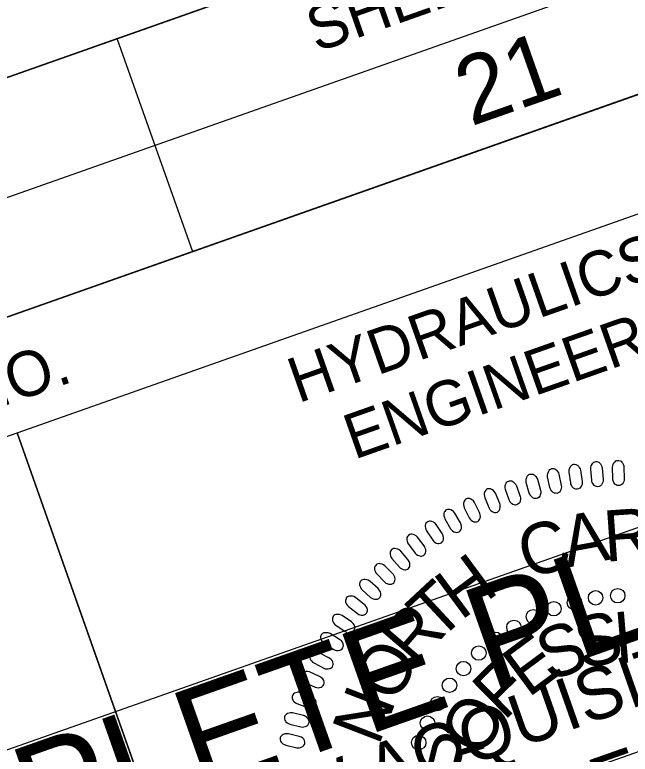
# Model space of a CAD drawing. Extents: x 473817 to 475769, y 501102 to 502694.
# Drawn here: x 475314.5 to 475382.8, y 502563 to 502645 of the extents above; entities that cross this region are included whole.
import ezdxf

# ---------------------------------------------------------------- set-up
doc = ezdxf.new("R2010")
doc.units = 0
for name, color, linetype in [('Sheet Data Field CELL', 7, 'Continuous'), ('Sheet PE Seal Cell', 7, 'Continuous'), ('Sheet Plan CELL', 7, 'Continuous'), ('Sheet Sticker Incomplete CELL', 7, 'Continuous')]:
    doc.layers.add(name, color=color, linetype=linetype)

msp = doc.modelspace()

# ---------------------------------------------------------------- linework, layer by layer
at = {"layer": 'Sheet PE Seal Cell'}
for points in [[(475376.159, 502593.075), (475375.976, 502594.288), (475375.98, 502594.511), (475376.011, 502594.656), (475376.096, 502594.841), (475376.176, 502594.964), (475376.274, 502595.059), (475376.372, 502595.114), (475376.48, 502595.151), (475376.594, 502595.148), (475376.717, 502595.136), (475376.829, 502595.093), (475376.947, 502595.01), (475377.018, 502594.94), (475377.107, 502594.802), (475377.194, 502594.634), (475377.24, 502594.479), (475377.435, 502593.238), (475377.438, 502593.067), (475377.414, 502592.922), (475377.35, 502592.751), (475377.26, 502592.596), (475377.176, 502592.503), (475377.029, 502592.42), (475376.884, 502592.378), (475376.731, 502592.395), (475376.62, 502592.429), (475376.479, 502592.508), (475376.336, 502592.658), (475376.242, 502592.825), (475376.193, 502592.949)], [(475378.491, 502593.395), (475378.383, 502594.617), (475378.402, 502594.838), (475378.442, 502594.983), (475378.538, 502595.161), (475378.625, 502595.279), (475378.73, 502595.368), (475378.831, 502595.417), (475378.941, 502595.447), (475379.055, 502595.437), (475379.177, 502595.417), (475379.286, 502595.367), (475379.398, 502595.277), (475379.465, 502595.203), (475379.545, 502595.059), (475379.621, 502594.886), (475379.658, 502594.728), (475379.774, 502593.477), (475379.766, 502593.307), (475379.733, 502593.164), (475379.658, 502592.997), (475379.559, 502592.848), (475379.469, 502592.76), (475379.318, 502592.687), (475379.171, 502592.654), (475379.018, 502592.681), (475378.91, 502592.721), (475378.775, 502592.809), (475378.64, 502592.968), (475378.558, 502593.141), (475378.517, 502593.267)], [(475380.819, 502593.556), (475380.789, 502594.783), (475380.821, 502595.004), (475380.87, 502595.144), (475380.978, 502595.317), (475381.073, 502595.428), (475381.183, 502595.511), (475381.286, 502595.553), (475381.398, 502595.576), (475381.511, 502595.559), (475381.631, 502595.531), (475381.738, 502595.474), (475381.844, 502595.377), (475381.906, 502595.299), (475381.977, 502595.151), (475382.041, 502594.973), (475382.067, 502594.814), (475382.105, 502593.558), (475382.088, 502593.388), (475382.046, 502593.247), (475381.96, 502593.085), (475381.851, 502592.943), (475381.756, 502592.861), (475381.601, 502592.797), (475381.451, 502592.774), (475381.301, 502592.81), (475381.196, 502592.858), (475381.066, 502592.954), (475380.942, 502593.12), (475380.87, 502593.298), (475380.838, 502593.427)], [(475373.857, 502592.567), (475373.598, 502593.766), (475373.588, 502593.989), (475373.61, 502594.136), (475373.684, 502594.325), (475373.756, 502594.454), (475373.849, 502594.555), (475373.942, 502594.616), (475374.047, 502594.659), (475374.162, 502594.663), (475374.284, 502594.66), (475374.399, 502594.623), (475374.523, 502594.548), (475374.598, 502594.483), (475374.696, 502594.351), (475374.792, 502594.188), (475374.847, 502594.037), (475375.121, 502592.81), (475375.134, 502592.639), (475375.12, 502592.494), (475375.066, 502592.319), (475374.986, 502592.159), (475374.908, 502592.06), (475374.767, 502591.968), (475374.625, 502591.917), (475374.471, 502591.925), (475374.358, 502591.951), (475374.212, 502592.022), (475374.06, 502592.162), (475373.956, 502592.324), (475373.899, 502592.444)], [(475371.571, 502591.947), (475371.237, 502593.127), (475371.213, 502593.349), (475371.226, 502593.497), (475371.288, 502593.691), (475371.351, 502593.823), (475371.437, 502593.93), (475371.527, 502593.997), (475371.63, 502594.047), (475371.743, 502594.058), (475371.866, 502594.062), (475371.983, 502594.033), (475372.111, 502593.966), (475372.19, 502593.905), (475372.296, 502593.779), (475372.402, 502593.623), (475372.467, 502593.476), (475372.816, 502592.268), (475372.841, 502592.099), (475372.836, 502591.953), (475372.793, 502591.775), (475372.723, 502591.61), (475372.652, 502591.506), (475372.517, 502591.406), (475372.378, 502591.346), (475372.224, 502591.344), (475372.109, 502591.364), (475371.96, 502591.425), (475371.799, 502591.555), (475371.685, 502591.709), (475371.621, 502591.827)], [(475369.337, 502591.187), (475368.93, 502592.344), (475368.892, 502592.564), (475368.896, 502592.713), (475368.945, 502592.91), (475369, 502593.046), (475369.079, 502593.158), (475369.165, 502593.231), (475369.264, 502593.287), (475369.376, 502593.305), (475369.499, 502593.317), (475369.617, 502593.295), (475369.749, 502593.236), (475369.833, 502593.18), (475369.945, 502593.062), (475370.062, 502592.912), (475370.136, 502592.769), (475370.56, 502591.587), (475370.596, 502591.419), (475370.599, 502591.272), (475370.568, 502591.092), (475370.509, 502590.923), (475370.443, 502590.816), (475370.315, 502590.707), (475370.181, 502590.639), (475370.027, 502590.627), (475369.912, 502590.639), (475369.758, 502590.69), (475369.589, 502590.811), (475369.466, 502590.958), (475369.395, 502591.07)], [(475368.289, 502590.808), (475367.809, 502591.937), (475367.689, 502592.125), (475367.587, 502592.232), (475367.417, 502592.345), (475367.285, 502592.408), (475367.15, 502592.438), (475367.039, 502592.434), (475366.927, 502592.408), (475366.832, 502592.345), (475366.734, 502592.272), (475366.66, 502592.176), (475366.603, 502592.043), (475366.58, 502591.946), (475366.576, 502591.782), (475366.591, 502591.593), (475366.633, 502591.438), (475367.117, 502590.278), (475367.204, 502590.131), (475367.3, 502590.02), (475367.444, 502589.908), (475367.603, 502589.824), (475367.723, 502589.788), (475367.891, 502589.794), (475368.037, 502589.834), (475368.159, 502589.929), (475368.235, 502590.016), (475368.313, 502590.158), (475368.357, 502590.36), (475368.348, 502590.552), (475368.326, 502590.683)], [(475366.057, 502589.806), (475365.507, 502590.903), (475365.376, 502591.083), (475365.266, 502591.184), (475365.09, 502591.285), (475364.954, 502591.34), (475364.818, 502591.361), (475364.707, 502591.35), (475364.597, 502591.317), (475364.506, 502591.249), (475364.413, 502591.169), (475364.346, 502591.069), (475364.297, 502590.933), (475364.279, 502590.834), (475364.286, 502590.67), (475364.313, 502590.483), (475364.364, 502590.331), (475364.92, 502589.204), (475365.016, 502589.062), (475365.119, 502588.957), (475365.271, 502588.855), (475365.433, 502588.78), (475365.556, 502588.753), (475365.723, 502588.769), (475365.866, 502588.818), (475365.982, 502588.921), (475366.053, 502589.012), (475366.122, 502589.159), (475366.153, 502589.363), (475366.132, 502589.554), (475366.101, 502589.683)], [(475363.933, 502588.667), (475363.317, 502589.727), (475363.174, 502589.898), (475363.058, 502589.993), (475362.876, 502590.083), (475362.737, 502590.128), (475362.6, 502590.141), (475362.49, 502590.123), (475362.382, 502590.084), (475362.295, 502590.01), (475362.207, 502589.924), (475362.147, 502589.82), (475362.106, 502589.68), (475362.095, 502589.582), (475362.112, 502589.418), (475362.151, 502589.234), (475362.212, 502589.084), (475362.837, 502587.995), (475362.942, 502587.859), (475363.051, 502587.761), (475363.209, 502587.668), (475363.376, 502587.604), (475363.5, 502587.584), (475363.666, 502587.611), (475363.805, 502587.67), (475363.914, 502587.779), (475363.98, 502587.875), (475364.039, 502588.025), (475364.057, 502588.231), (475364.025, 502588.42), (475363.985, 502588.547)], [(475361.916, 502587.455), (475361.234, 502588.474), (475361.081, 502588.636), (475360.959, 502588.723), (475360.772, 502588.802), (475360.63, 502588.838), (475360.493, 502588.842), (475360.383, 502588.818), (475360.279, 502588.772), (475360.197, 502588.693), (475360.115, 502588.601), (475360.061, 502588.493), (475360.029, 502588.352), (475360.024, 502588.253), (475360.051, 502588.091), (475360.101, 502587.909), (475360.171, 502587.764), (475360.865, 502586.715), (475360.977, 502586.587), (475361.092, 502586.496), (475361.256, 502586.413), (475361.427, 502586.359), (475361.551, 502586.348), (475361.716, 502586.385), (475361.851, 502586.451), (475361.953, 502586.568), (475362.012, 502586.667), (475362.062, 502586.821), (475362.067, 502587.028), (475362.023, 502587.215), (475361.976, 502587.339)], [(475359.922, 502586.094), (475359.177, 502587.068), (475359.014, 502587.22), (475358.888, 502587.299), (475358.696, 502587.366), (475358.552, 502587.394), (475358.414, 502587.389), (475358.306, 502587.357), (475358.206, 502587.305), (475358.128, 502587.221), (475358.052, 502587.125), (475358.005, 502587.014), (475357.982, 502586.871), (475357.983, 502586.771), (475358.021, 502586.611), (475358.082, 502586.432), (475358.161, 502586.292), (475358.919, 502585.289), (475359.04, 502585.168), (475359.16, 502585.085), (475359.328, 502585.012), (475359.502, 502584.97), (475359.627, 502584.965), (475359.789, 502585.013), (475359.919, 502585.088), (475360.014, 502585.21), (475360.067, 502585.314), (475360.107, 502585.47), (475360.099, 502585.677), (475360.044, 502585.861), (475359.989, 502585.982)], [(475358.118, 502584.592), (475357.313, 502585.518), (475357.14, 502585.659), (475357.01, 502585.73), (475356.814, 502585.785), (475356.669, 502585.804), (475356.532, 502585.79), (475356.426, 502585.752), (475356.329, 502585.693), (475356.257, 502585.604), (475356.186, 502585.503), (475356.147, 502585.389), (475356.133, 502585.245), (475356.141, 502585.146), (475356.188, 502584.989), (475356.261, 502584.814), (475356.348, 502584.679), (475357.167, 502583.726), (475357.295, 502583.613), (475357.421, 502583.537), (475357.593, 502583.475), (475357.769, 502583.443), (475357.895, 502583.447), (475358.053, 502583.505), (475358.179, 502583.588), (475358.265, 502583.716), (475358.311, 502583.822), (475358.342, 502583.981), (475358.322, 502584.188), (475358.254, 502584.367), (475358.192, 502584.485)], [(475356.431, 502583.008), (475355.57, 502583.882), (475355.389, 502584.011), (475355.254, 502584.074), (475355.055, 502584.117), (475354.909, 502584.126), (475354.773, 502584.104), (475354.67, 502584.059), (475354.576, 502583.995), (475354.511, 502583.902), (475354.446, 502583.797), (475354.414, 502583.681), (475354.409, 502583.536), (475354.423, 502583.437), (475354.48, 502583.283), (475354.564, 502583.113), (475354.659, 502582.984), (475355.537, 502582.085), (475355.672, 502581.979), (475355.802, 502581.911), (475355.978, 502581.861), (475356.156, 502581.84), (475356.28, 502581.852), (475356.434, 502581.919), (475356.555, 502582.01), (475356.633, 502582.144), (475356.673, 502582.252), (475356.693, 502582.412), (475356.66, 502582.617), (475356.581, 502582.792), (475356.512, 502582.906)], [(475354.804, 502581.359), (475353.889, 502582.177), (475353.7, 502582.296), (475353.562, 502582.35), (475353.361, 502582.379), (475353.214, 502582.38), (475353.08, 502582.349), (475352.981, 502582.298), (475352.891, 502582.227), (475352.831, 502582.131), (475352.773, 502582.022), (475352.748, 502581.904), (475352.753, 502581.759), (475352.773, 502581.661), (475352.839, 502581.511), (475352.933, 502581.347), (475353.037, 502581.224), (475353.969, 502580.381), (475354.11, 502580.285), (475354.244, 502580.225), (475354.423, 502580.186), (475354.602, 502580.176), (475354.726, 502580.195), (475354.876, 502580.273), (475354.99, 502580.371), (475355.06, 502580.509), (475355.093, 502580.62), (475355.103, 502580.781), (475355.056, 502580.983), (475354.967, 502581.153), (475354.89, 502581.262)], [(475353.281, 502579.611), (475352.317, 502580.37), (475352.121, 502580.476), (475351.979, 502580.522), (475351.777, 502580.539), (475351.63, 502580.53), (475351.499, 502580.491), (475351.402, 502580.434), (475351.317, 502580.358), (475351.263, 502580.257), (475351.213, 502580.145), (475351.195, 502580.026), (475351.209, 502579.882), (475351.235, 502579.785), (475351.311, 502579.64), (475351.415, 502579.482), (475351.526, 502579.365), (475352.51, 502578.583), (475352.657, 502578.495), (475352.794, 502578.444), (475352.975, 502578.416), (475353.154, 502578.418), (475353.277, 502578.445), (475353.421, 502578.531), (475353.529, 502578.637), (475353.59, 502578.779), (475353.616, 502578.892), (475353.616, 502579.053), (475353.556, 502579.252), (475353.457, 502579.416), (475353.374, 502579.519)], [(475351.845, 502577.669), (475350.835, 502578.365), (475350.633, 502578.459), (475350.488, 502578.496), (475350.285, 502578.499), (475350.139, 502578.481), (475350.01, 502578.434), (475349.918, 502578.371), (475349.838, 502578.29), (475349.791, 502578.186), (475349.747, 502578.071), (475349.737, 502577.951), (475349.76, 502577.808), (475349.791, 502577.714), (475349.877, 502577.573), (475349.99, 502577.422), (475350.109, 502577.313), (475351.139, 502576.593), (475351.292, 502576.516), (475351.432, 502576.473), (475351.614, 502576.456), (475351.793, 502576.469), (475351.914, 502576.504), (475352.052, 502576.599), (475352.153, 502576.711), (475352.205, 502576.857), (475352.223, 502576.971), (475352.214, 502577.132), (475352.142, 502577.327), (475352.032, 502577.485), (475351.943, 502577.583)], [(475350.533, 502575.733), (475349.481, 502576.365), (475349.274, 502576.446), (475349.128, 502576.473), (475348.925, 502576.464), (475348.781, 502576.438), (475348.654, 502576.383), (475348.567, 502576.313), (475348.492, 502576.227), (475348.451, 502576.121), (475348.415, 502576.003), (475348.412, 502575.883), (475348.444, 502575.741), (475348.481, 502575.649), (475348.575, 502575.514), (475348.698, 502575.37), (475348.824, 502575.269), (475349.896, 502574.615), (475350.054, 502574.548), (475350.196, 502574.514), (475350.379, 502574.509), (475350.556, 502574.533), (475350.675, 502574.575), (475350.807, 502574.679), (475350.901, 502574.797), (475350.944, 502574.946), (475350.955, 502575.061), (475350.935, 502575.221), (475350.851, 502575.411), (475350.732, 502575.561), (475350.636, 502575.654)], [(475349.359, 502573.687), (475348.27, 502574.252), (475348.058, 502574.32), (475347.909, 502574.338), (475347.707, 502574.316), (475347.566, 502574.281), (475347.443, 502574.218), (475347.359, 502574.143), (475347.29, 502574.053), (475347.256, 502573.944), (475347.228, 502573.823), (475347.232, 502573.703), (475347.273, 502573.564), (475347.316, 502573.475), (475347.418, 502573.346), (475347.55, 502573.211), (475347.681, 502573.117), (475348.794, 502572.532), (475348.954, 502572.474), (475349.099, 502572.45), (475349.282, 502572.456), (475349.458, 502572.491), (475349.574, 502572.54), (475349.699, 502572.653), (475349.785, 502572.777), (475349.818, 502572.927), (475349.823, 502573.043), (475349.793, 502573.202), (475349.697, 502573.386), (475349.568, 502573.528), (475349.467, 502573.615)], [(475348.326, 502571.617), (475347.204, 502572.112), (475346.988, 502572.166), (475346.839, 502572.175), (475346.638, 502572.141), (475346.499, 502572.096), (475346.381, 502572.025), (475346.303, 502571.946), (475346.239, 502571.851), (475346.212, 502571.741), (475346.191, 502571.619), (475346.203, 502571.5), (475346.252, 502571.363), (475346.301, 502571.276), (475346.411, 502571.154), (475346.551, 502571.027), (475346.688, 502570.942), (475347.835, 502570.428), (475347.999, 502570.381), (475348.145, 502570.365), (475348.327, 502570.383), (475348.5, 502570.429), (475348.612, 502570.486), (475348.731, 502570.605), (475348.809, 502570.734), (475348.832, 502570.887), (475348.829, 502571.003), (475348.789, 502571.16), (475348.682, 502571.338), (475348.545, 502571.471), (475348.439, 502571.551)], [(475347.399, 502569.395), (475346.248, 502569.819), (475346.029, 502569.859), (475345.88, 502569.859), (475345.682, 502569.812), (475345.545, 502569.759), (475345.432, 502569.681), (475345.359, 502569.597), (475345.301, 502569.498), (475345.281, 502569.386), (475345.268, 502569.263), (475345.287, 502569.145), (475345.345, 502569.012), (475345.399, 502568.928), (475345.517, 502568.813), (475345.665, 502568.695), (475345.806, 502568.619), (475346.983, 502568.178), (475347.15, 502568.141), (475347.296, 502568.135), (475347.477, 502568.164), (475347.647, 502568.221), (475347.755, 502568.285), (475347.866, 502568.411), (475347.936, 502568.544), (475347.95, 502568.699), (475347.94, 502568.814), (475347.89, 502568.968), (475347.772, 502569.138), (475347.627, 502569.264), (475347.515, 502569.336)], [(475346.527, 502567.283), (475345.334, 502567.568), (475345.112, 502567.583), (475344.964, 502567.565), (475344.773, 502567.495), (475344.644, 502567.426), (475344.541, 502567.335), (475344.478, 502567.243), (475344.432, 502567.138), (475344.425, 502567.025), (475344.427, 502566.901), (475344.46, 502566.786), (475344.533, 502566.661), (475344.596, 502566.584), (475344.726, 502566.484), (475344.887, 502566.384), (475345.037, 502566.325), (475346.257, 502566.026), (475346.428, 502566.008), (475346.574, 502566.019), (475346.75, 502566.069), (475346.911, 502566.146), (475347.012, 502566.222), (475347.106, 502566.361), (475347.16, 502566.501), (475347.157, 502566.656), (475347.132, 502566.769), (475347.065, 502566.916), (475346.928, 502567.072), (475346.769, 502567.179), (475346.65, 502567.238)], [(475346.055, 502564.971), (475344.86, 502565.247), (475344.637, 502565.26), (475344.49, 502565.241), (475344.298, 502565.17), (475344.17, 502565.1), (475344.067, 502565.009), (475344.005, 502564.915), (475343.96, 502564.81), (475343.955, 502564.696), (475343.957, 502564.574), (475343.991, 502564.458), (475344.065, 502564.334), (475344.129, 502564.257), (475344.26, 502564.158), (475344.421, 502564.059), (475344.572, 502564.002), (475345.795, 502563.712), (475345.965, 502563.696), (475346.111, 502563.708), (475346.286, 502563.76), (475346.448, 502563.837), (475346.548, 502563.914), (475346.641, 502564.054), (475346.694, 502564.195), (475346.689, 502564.349), (475346.664, 502564.463), (475346.595, 502564.609), (475346.457, 502564.763), (475346.297, 502564.869), (475346.177, 502564.928)]]:
    msp.add_lwpolyline(points, close=True, dxfattribs=at)
for centre in [(475378.924, 502580.341), (475381.376, 502580.571), (475376.579, 502579.811), (475374.286, 502579.13), (475372.022, 502578.248), (475369.863, 502577.065), (475367.795, 502575.746), (475365.97, 502574.216), (475364.272, 502572.492), (475362.73, 502570.64), (475361.38, 502568.601), (475360.283, 502566.441), (475359.313, 502564.283)]:
    msp.add_circle(centre, 0.801, dxfattribs=at)
at = {"layer": 'Sheet Plan CELL'}
for p, q in [((475212.116, 502588.952), (475400.785, 502655.465)), ((475216.297, 502577.132), (475404.942, 502643.676)), ((475216.297, 502577.132), (475404.942, 502643.676)), ((475325.877, 502642.293), (475334.238, 502618.732)), ((475314.805, 502598.626), (475352.215, 502492.568))]:
    msp.add_line(p, q, dxfattribs=at)
for points in [[(475396.647, 502667.313), (473981.977, 502168.491), (474331.144, 501178.248), (475745.79, 501677.061)], [(475207.954, 502600.792), (475396.647, 502667.313), (475404.942, 502643.676), (475216.297, 502577.132)], [(475314.805, 502598.626), (475409.098, 502631.888), (475446.525, 502525.783), (475352.22, 502492.517)], [(475220.449, 502565.356), (475314.805, 502598.626), (475352.22, 502492.517), (475257.868, 502459.274)]]:
    msp.add_lwpolyline(points, close=True, dxfattribs=at)
at = {"layer": 'Sheet Sticker Incomplete CELL'}
msp.add_lwpolyline([(475264.194, 502521.136), (475256.379, 502543.298), (475395.013, 502592.182), (475402.828, 502570.019)], close=True, dxfattribs=at)

# ---------------------------------------------------------------- texts
at = {"layer": 'Sheet Data Field CELL'}
msp.add_text('21', height=7.5, rotation=19.42299, dxfattribs=at).set_placement((475365.089, 502632.593))
at = {"layer": 'Sheet PE Seal Cell'}
for s, height, rotation, p in [('R', 5.669, 4.03196, (475379.981, 502584.328)), ('A', 5.669, 10.52131, (475375.75, 502583.679)), ('C', 5.669, 17.01067, (475371.365, 502582.354)), ('H', 5.669, 36.47874, (475363.971, 502577.749)), ('T', 5.669, 42.96809, (475361.441, 502575.362)), ('R', 5.669, 49.45745, (475359.042, 502572.482)), ('S', 5.669, 12.77222, (475377.341, 502572.381)), ('I', 5.669, 4.83243, (475381.135, 502573.05)), ('S', 5.669, 20.71202, (475373.734, 502571.002)), ('E', 5.669, 36.59162, (475371.443, 502569.177)), ('O', 5.669, 62.43617, (475356.771, 502568.47)), ('F', 5.669, 44.53141, (475368.757, 502566.599)), ('N', 5.669, 68.92552, (475354.864, 502563.815)), ('O', 5.669, 60.41101, (475366.314, 502562.409)), ('SEAL', 6.2363, 19.40435, (475374.413, 502554.389)), ('R', 5.669, 76.29061, (475365.545, 502559.438))]:
    msp.add_text(s, height=height, rotation=rotation, dxfattribs=at).set_placement(p)
at = {"layer": 'Sheet Plan CELL'}
for s, p in [('SHEET NO.', (475347.983, 502640.796)), ('HYDRAULICS', (475345.953, 502601.895)), ('ENGINEER', (475352.15, 502595.637)), ('R/W SHEET NO.', (475273.108, 502587.423))]:
    msp.add_text(s, height=5.0001, rotation=19.42299, dxfattribs=at).set_placement(p)
at = {"layer": 'Sheet Sticker Incomplete CELL'}
for s, height, p in [('INCOMPLETE PLANS', 11.52, (475268.744, 502535.146)), ('DO NOT USE FOR R/W ACQUISITION', 5.76, (475274.12, 502529.672))]:
    msp.add_text(s, height=height, rotation=19.42299, dxfattribs=at).set_placement(p)

doc.saveas('drawing.dxf')
